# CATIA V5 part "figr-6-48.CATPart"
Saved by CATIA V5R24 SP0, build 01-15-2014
Part number: Part1
Bounding box of the stored display mesh (mm): x 0 to 100, y -60 to 60, z -50 to 50
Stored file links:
  D:\KAVITA\CATIA V5-6R2014 Project_ Kavita\CATIA V5-6R2014_partfiles\Partfiles\c06_catia_v5-6r2014_prt\figr-6-48.CATPart
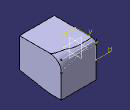
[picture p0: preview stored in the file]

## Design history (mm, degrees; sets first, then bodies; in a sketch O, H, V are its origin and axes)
Body1 (main body)
  Sketch1 on yz-plane, origin (0, 0, 0), H (0, 1, 0), V (0, 0, 1)
    line L1 (60, 50) -> (60, -50)
    line L2 (60, -50) -> (25, -50)
    line L3 (-60, -35) -> (-60, 50)
    line L4 (-60, 50) -> (60, 50)
    point P2 (60, -50)
    point P3 (-60, -50)
    line L5 (25, -50) -> (-60, -35)
    point P5 (25, -50)
    point P6 (-60, -35)
    length L1 = 100
    distance P2 P3 = 120
    distance P5 P3 = 85
    distance P6 P3 = 15
    vertical: L1 V, L3 V
    horizontal: L2 H, L4 H
    equidistance: L1 L3 O, L2 L4 O
    coincidence: L2 P3, L3 P3
  Pad1: profile Sketch1, direction (1, 0, 0), length 100
  Sketch2 on face of Pad1 from Sketch1.L1, origin (0, 60, 0), H (-1, 0, 0), V (0, 0, 1)
    spline S1 through (-100, 18.28) (-85.0256, 26.4663) (-71, 29) (-63.0256, 32.4663) (-31, 39) (-16, 39) (0, 37.4663)
    reference projected line E1 (-100, -50) -> (-100, 50) from edge [face of Pad1 from Sketch1.L1 | end face of Pad1]
    reference projected line E2 (0, -50) -> (0, 50) from edge [start face of Pad1 | face of Pad1 from Sketch1.L1]
    point P1 (0, 37.4663)
    point P2 (-100, 18.28)
    coincidence: P1 V, P2 E1, P1 E2
  Sketch3 on face of Pad1 from Sketch1.L4, origin (0, 0, 50), H (1, 0, 0), V (0, 1, 0)
    projected line E1 (0, 60) -> (100, 60) from Sketch2.S1
  FaceFillet1: ConicRatio 0.5, Face1 face of Pad1 from Sketch1.L1, Face2 face of Pad1 from Sketch1.L4, HoldCurve Sketch2, Radius 5, Spine Sketch3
